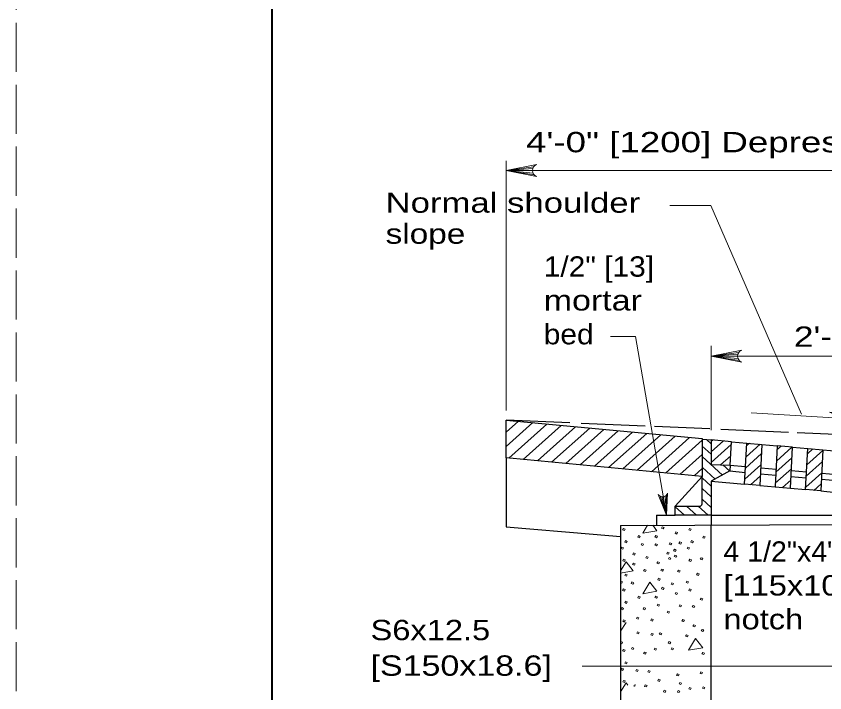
# Model space of a CAD drawing. Extents: x -1431.2 to -1397.2, y -1045.1 to -1001.1.
# Drawn here: x -1431.25 to -1424.93, y -1040.42 to -1035.13 of the extents above; entities that cross this region are included whole.
import ezdxf

# ---------------------------------------------------------------- set-up
doc = ezdxf.new("R2010")
doc.units = 0
doc.header["$LTSCALE"] = 0.064
doc.linetypes.add('LONG_DASHED', pattern=[7.5, 6, -1.5])
doc.layers.add('1', color=7, linetype='Continuous', lineweight=13)

msp = doc.modelspace()

# ---------------------------------------------------------------- linework, layer by layer
at = {"layer": '1'}
for p, q in [((-1427.4155, -1038.20883), (-1427.4155, -1036.25842)), ((-1427.20033, -1036.30475), (-1427.4155, -1036.33483)), ((-1427.20758, -1036.31967), (-1427.4155, -1036.33483)), ((-1423.10775, -1036.33483), (-1427.4155, -1036.33483)), ((-1427.20983, -1036.33483), (-1427.4155, -1036.33483)), ((-1427.206, -1036.35417), (-1427.4155, -1036.33483)), ((-1427.19775, -1036.36817), (-1427.4155, -1036.33483)), ((-1425.81283, -1038.363), (-1425.81283, -1037.705)), ((-1425.59767, -1037.75533), (-1425.81283, -1037.78542)), ((-1425.60492, -1037.77025), (-1425.81283, -1037.78542)), ((-1425.60717, -1037.78542), (-1425.81283, -1037.78542)), ((-1425.60333, -1037.80475), (-1425.81283, -1037.78542)), ((-1425.59508, -1037.81875), (-1425.81283, -1037.78542)), ((-1423.1035, -1037.78542), (-1425.81283, -1037.78542)), ((-1427.4155, -1038.38025), (-1427.32, -1038.29433)), ((-1427.4155, -1038.491), (-1427.20867, -1038.30483)), ((-1427.39458, -1038.58283), (-1427.09725, -1038.31533)), ((-1427.28325, -1038.59333), (-1426.98592, -1038.32583)), ((-1427.17183, -1038.60383), (-1426.87467, -1038.33633)), ((-1427.0605, -1038.61433), (-1426.76325, -1038.34683)), ((-1426.94908, -1038.62483), (-1426.65192, -1038.35733)), ((-1426.83775, -1038.63533), (-1426.5405, -1038.36775)), ((-1426.72642, -1038.64583), (-1426.42917, -1038.37833)), ((-1426.61508, -1038.65633), (-1426.31775, -1038.38883)), ((-1426.50375, -1038.66683), (-1426.20642, -1038.39933)), ((-1426.39233, -1038.67733), (-1426.09508, -1038.40975)), ((-1426.281, -1038.68783), (-1425.98367, -1038.42025)), ((-1426.16967, -1038.69833), (-1425.88467, -1038.44192)), ((-1425.88467, -1038.42967), (-1425.88467, -1038.43308)), ((-1425.81283, -1038.469), (-1425.84933, -1038.43617)), ((-1425.81283, -1038.45083), (-1425.80125, -1038.4405)), ((-1425.81283, -1038.534), (-1425.71733, -1038.448)), ((-1425.81283, -1038.55208), (-1425.88467, -1038.4875)), ((-1425.81283, -1038.617), (-1425.65617, -1038.476)), ((-1425.54133, -1038.57275), (-1425.431, -1038.4735)), ((-1425.537, -1038.48583), (-1425.515, -1038.46608)), ((-1425.3035, -1038.605), (-1425.18208, -1038.49567)), ((-1425.29925, -1038.51808), (-1425.266, -1038.48817)), ((-1425.06133, -1038.54817), (-1425.01908, -1038.51017)), ((-1426.05825, -1038.70883), (-1425.88467, -1038.55258)), ((-1425.72475, -1038.71433), (-1425.88467, -1038.5705)), ((-1425.73942, -1038.634), (-1425.6605, -1038.56292)), ((-1425.54575, -1038.65975), (-1425.42033, -1038.54683)), ((-1425.30783, -1038.69192), (-1425.1825, -1038.57917)), ((-1425.06575, -1038.63517), (-1424.94033, -1038.52233)), ((-1425.66733, -1038.683), (-1425.72125, -1038.6345)), ((-1425.55008, -1038.74675), (-1425.42467, -1038.63375)), ((-1425.07008, -1038.72208), (-1424.94467, -1038.60925)), ((-1425.94692, -1038.71933), (-1425.88467, -1038.66333)), ((-1425.78217, -1038.74575), (-1425.88467, -1038.6535)), ((-1425.31217, -1038.77875), (-1425.18683, -1038.66608)), ((-1425.07433, -1038.809), (-1424.94892, -1038.69617)), ((-1425.81283, -1038.80117), (-1425.88467, -1038.73658)), ((-1425.50583, -1038.78983), (-1425.429, -1038.72083)), ((-1425.25683, -1038.81208), (-1425.19125, -1038.753)), ((-1425.81283, -1038.88417), (-1425.88467, -1038.81958)), ((-1425.00992, -1038.834), (-1424.95325, -1038.78308)), ((-1426.212, -1038.87983), (-1426.1615, -1039.02842)), ((-1426.19958, -1038.88358), (-1426.1615, -1039.02842)), ((-1426.1875, -1038.88375), (-1426.1615, -1039.02842)), ((-1426.173, -1038.87933), (-1426.1615, -1039.02842)), ((-1426.16325, -1038.87217), (-1426.1615, -1039.02842)), ((-1426.02167, -1039.02842), (-1426.09542, -1038.962)), ((-1425.92942, -1039.02842), (-1426.00742, -1038.95817)), ((-1425.83717, -1039.02842), (-1425.91517, -1038.95817)), ((-1425.81283, -1038.96725), (-1425.88467, -1038.90267)), ((-1426.47917, -1039.39308), (-1426.52183, -1039.46183)), ((-1426.52183, -1039.54717), (-1426.52, -1039.54317)), ((-1426.47917, -1039.86608), (-1426.52183, -1039.93483)), ((-1426.52183, -1040.02008), (-1426.52, -1040.01608)), ((-1426.47917, -1040.339), (-1426.52183, -1040.40783)), ((-1426.46617, -1040.35575), (-1426.47917, -1040.339)), ((-1426.4115, -1040.35208), (-1426.40883, -1040.35317))]:
    msp.add_line(p, q, dxfattribs=at)
at = {"layer": '1', "lineweight": 25}
for p, q in [((-1426.91775, -1038.30683), (-1427.4155, -1038.28533)), ((-1427.4155, -1038.28533), (-1425.88425, -1038.42967)), ((-1426.3285, -1038.33242), (-1426.829, -1038.31067)), ((-1425.82308, -1038.35433), (-1426.25733, -1038.3355)), ((-1425.21017, -1038.38083), (-1425.73708, -1038.358)), ((-1424.63183, -1038.40583), (-1425.14108, -1038.38383)), ((-1425.65508, -1038.45358), (-1425.81283, -1038.4395)), ((-1425.66425, -1038.63642), (-1425.65508, -1038.45358)), ((-1425.65508, -1038.45358), (-1425.53592, -1038.46417)), ((-1425.41667, -1038.47475), (-1425.29758, -1038.48533)), ((-1425.17833, -1038.496), (-1425.05917, -1038.50658)), ((-1425.07533, -1038.82817), (-1425.05925, -1038.50658)), ((-1425.05917, -1038.50658), (-1424.93992, -1038.51717)), ((-1424.93992, -1038.51717), (-1424.82083, -1038.52775)), ((-1427.4155, -1038.58083), (-1427.4155, -1039.11925)), ((-1425.66733, -1038.63617), (-1425.54508, -1038.647)), ((-1425.6665, -1038.68258), (-1425.54742, -1038.69317)), ((-1425.42817, -1038.70375), (-1425.30892, -1038.71433)), ((-1425.42583, -1038.65767), (-1425.30667, -1038.66825)), ((-1425.1875, -1038.67892), (-1425.06842, -1038.6895)), ((-1424.94917, -1038.70008), (-1424.83008, -1038.71067)), ((-1425.88467, -1038.72525), (-1426.09542, -1038.95817)), ((-1425.88467, -1038.93858), (-1425.88467, -1038.72525)), ((-1425.81283, -1038.76258), (-1425.55208, -1038.78583)), ((-1425.18983, -1038.725), (-1425.07067, -1038.73567)), ((-1424.95142, -1038.74625), (-1424.83233, -1038.75683)), ((-1425.43283, -1038.79642), (-1425.31358, -1038.807)), ((-1425.1945, -1038.81758), (-1425.07533, -1038.82817)), ((-1424.95608, -1038.83883), (-1424.837, -1038.84942)), ((-1426.24008, -1039.02842), (-1426.24008, -1039.10625)), ((-1426.24008, -1039.02842), (-1426.09542, -1039.02842)), ((-1425.81283, -1039.02842), (-1423.1035, -1039.02842)), ((-1426.52183, -1039.1075), (-1422.72758, -1039.09133)), ((-1426.52183, -1039.1075), (-1426.52183, -1041.37567)), ((-1425.81283, -1040.04383), (-1425.81283, -1039.1045)), ((-1425.81283, -1041.37325), (-1425.81283, -1040.04383))]:
    msp.add_line(p, q, dxfattribs=at)
at = {"layer": '1', "linetype": 'LONG_DASHED'}
msp.add_lwpolyline([(-1431.24575, -1045.07983), (-1397.24575, -1045.07983), (-1397.24575, -1023.07983), (-1431.24575, -1023.07983)], close=True, dxfattribs=at)
at = {"layer": '1', "lineweight": 25}
for points in [[(-1397.74575, -1044.57983), (-1429.24575, -1044.57983), (-1429.24575, -1023.57983)], [(-1425.88467, -1038.42967), (-1425.88467, -1038.72525), (-1427.4155, -1038.58083), (-1427.4155, -1038.28533)], [(-1425.88467, -1038.43308), (-1425.81283, -1038.4395), (-1425.81283, -1038.63175), (-1425.66733, -1038.63617)], [(-1424.94, -1038.51717), (-1424.95608, -1038.83883), (-1425.07533, -1038.82817)], [(-1425.66417, -1038.63642), (-1425.6665, -1038.68258), (-1425.81283, -1038.7625), (-1425.81283, -1039.1045)], [(-1425.81283, -1039.02842), (-1426.09542, -1039.02842), (-1426.09542, -1038.95817), (-1425.90633, -1038.95817)], [(-1427.4155, -1039.11925), (-1426.73658, -1039.17567), (-1426.52183, -1039.1935)]]:
    msp.add_lwpolyline(points, dxfattribs=at)
at = {"layer": '1', "lineweight": 40}
msp.add_lwpolyline([(-1429.24575, -1023.57983), (-1397.74575, -1023.57983), (-1397.74575, -1044.57983), (-1429.24575, -1044.57983)], close=True, dxfattribs=at)
at = {"layer": '1'}
for points in [[(-1427.17783, -1036.38242), (-1427.4155, -1036.33483), (-1427.17783, -1036.28733)], [(-1425.10825, -1038.23842), (-1425.81675, -1036.60825), (-1426.13675, -1036.60825)], [(-1426.1615, -1039.02842), (-1426.40542, -1037.63133), (-1426.5995, -1037.63133)], [(-1425.57508, -1037.833), (-1425.81283, -1037.78542), (-1425.57508, -1037.73792)], [(-1425.502, -1038.22842), (-1424.33817, -1038.29833), (-1424.88758, -1038.22325), (-1424.77525, -1038.27042)], [(-1426.15475, -1038.85675), (-1426.1615, -1039.02842), (-1426.22833, -1038.86558)], [(-1426.31008, -1039.10658), (-1426.34867, -1039.16883), (-1426.23725, -1039.14925), (-1426.27058, -1039.10642)], [(-1426.52183, -1039.48125), (-1426.42392, -1039.464), (-1426.47917, -1039.39308)], [(-1426.52, -1039.54317), (-1426.50633, -1039.548), (-1426.51183, -1039.56025), (-1426.52183, -1039.556)], [(-1422.76167, -1039.67058), (-1424.21225, -1040.20775), (-1426.82292, -1040.20775)], [(-1426.52, -1040.01608), (-1426.50633, -1040.021), (-1426.51183, -1040.03325), (-1426.52183, -1040.029)], [(-1426.40883, -1040.35592), (-1426.41392, -1040.36517), (-1426.42183, -1040.36233)]]:
    msp.add_lwpolyline(points, dxfattribs=at)
at = {"layer": '1', "lineweight": 25}
for points in [[(-1425.55208, -1038.78583), (-1425.53592, -1038.46417), (-1425.41667, -1038.47475), (-1425.43283, -1038.79642)], [(-1425.17833, -1038.496), (-1425.29758, -1038.48533), (-1425.31358, -1038.807), (-1425.1945, -1038.81758)]]:
    msp.add_lwpolyline(points, close=True, dxfattribs=at)
at = {"layer": '1'}
for points in [[(-1426.49908, -1039.13133), (-1426.4855, -1039.13625), (-1426.49183, -1039.14758), (-1426.50542, -1039.14275)], [(-1426.1955, -1039.11825), (-1426.18192, -1039.124), (-1426.18825, -1039.13542), (-1426.20192, -1039.1305)], [(-1425.98258, -1039.13133), (-1425.969, -1039.13625), (-1425.97533, -1039.14758), (-1425.98892, -1039.14275)], [(-1426.38225, -1039.18758), (-1426.36858, -1039.19325), (-1426.37408, -1039.20467), (-1426.38767, -1039.19983)], [(-1426.24717, -1039.18758), (-1426.23358, -1039.1925), (-1426.23992, -1039.20392), (-1426.2535, -1039.199)], [(-1426.0895, -1039.15825), (-1426.07592, -1039.16308), (-1426.08133, -1039.17533), (-1426.09492, -1039.16967)], [(-1425.873, -1039.19242), (-1425.85942, -1039.19733), (-1425.86575, -1039.20875), (-1425.87942, -1039.20383)], [(-1426.51267, -1039.27725), (-1426.49908, -1039.283), (-1426.50458, -1039.29442), (-1426.51817, -1039.28867)], [(-1426.48275, -1039.22675), (-1426.46917, -1039.23242), (-1426.47558, -1039.24383), (-1426.48917, -1039.23817)], [(-1426.355, -1039.24875), (-1426.34142, -1039.25442), (-1426.34692, -1039.26583), (-1426.3605, -1039.26017)], [(-1426.24717, -1039.25117), (-1426.23358, -1039.25608), (-1426.23992, -1039.26833), (-1426.2535, -1039.26258)], [(-1426.13575, -1039.243), (-1426.12217, -1039.24875), (-1426.12758, -1039.26017), (-1426.14117, -1039.25525)], [(-1426.05867, -1039.2365), (-1426.04508, -1039.24142), (-1426.05142, -1039.25367), (-1426.06508, -1039.24792)], [(-1425.99617, -1039.27725), (-1425.98258, -1039.283), (-1425.988, -1039.29442), (-1426.00158, -1039.28867)], [(-1425.96625, -1039.22675), (-1425.95267, -1039.23242), (-1425.959, -1039.24383), (-1425.97258, -1039.23817)], [(-1426.42025, -1039.32217), (-1426.40667, -1039.32783), (-1426.41208, -1039.33925), (-1426.42575, -1039.33433)], [(-1426.15567, -1039.31725), (-1426.14208, -1039.32217), (-1426.1475, -1039.33358), (-1426.16108, -1039.32867)], [(-1426.10125, -1039.29442), (-1426.08767, -1039.30008), (-1426.09317, -1039.3115), (-1426.10675, -1039.30667)], [(-1426.09675, -1039.33925), (-1426.08317, -1039.345), (-1426.08858, -1039.35642), (-1426.10217, -1039.35067)], [(-1426.49817, -1039.37267), (-1426.48458, -1039.37758), (-1426.49008, -1039.38983), (-1426.50367, -1039.38408)], [(-1426.42117, -1039.40208), (-1426.40758, -1039.40775), (-1426.41392, -1039.41917), (-1426.4275, -1039.41425)], [(-1426.31875, -1039.34983), (-1426.30517, -1039.35475), (-1426.3115, -1039.367), (-1426.32508, -1039.36125)], [(-1426.23175, -1039.39225), (-1426.21817, -1039.39717), (-1426.22367, -1039.40858), (-1426.23725, -1039.40367)], [(-1426.14117, -1039.358), (-1426.12758, -1039.36375), (-1426.133, -1039.37517), (-1426.14658, -1039.36942)], [(-1425.98167, -1039.37267), (-1425.96808, -1039.37758), (-1425.9735, -1039.38983), (-1425.98708, -1039.38408)], [(-1425.89217, -1039.36), (-1425.87858, -1039.36483), (-1425.88492, -1039.37625), (-1425.8985, -1039.37142)], [(-1426.336, -1039.45183), (-1426.32242, -1039.45667), (-1426.32783, -1039.46808), (-1426.34142, -1039.46325)], [(-1426.201, -1039.4485), (-1426.18742, -1039.45342), (-1426.19375, -1039.46483), (-1426.20733, -1039.45992)], [(-1426.06958, -1039.45667), (-1426.056, -1039.46158), (-1426.06233, -1039.473), (-1426.07592, -1039.46808)], [(-1426.48275, -1039.4885), (-1426.46917, -1039.49342), (-1426.47467, -1039.50558), (-1426.48825, -1039.49992)], [(-1426.22542, -1039.52108), (-1426.21183, -1039.526), (-1426.21725, -1039.53742), (-1426.23092, -1039.5325)], [(-1425.92092, -1039.48208), (-1425.90733, -1039.48692), (-1425.91367, -1039.49833), (-1425.92725, -1039.4935)], [(-1426.433, -1039.54967), (-1426.41933, -1039.55533), (-1426.42483, -1039.56675), (-1426.43842, -1039.56192)], [(-1426.2925, -1039.55125), (-1426.34867, -1039.64183), (-1426.23725, -1039.62225)], [(-1426.1955, -1039.59125), (-1426.18192, -1039.59692), (-1426.18825, -1039.60833), (-1426.20192, -1039.6035)], [(-1426.12033, -1039.55533), (-1426.10675, -1039.56108), (-1426.11217, -1039.5725), (-1426.12575, -1039.56675)], [(-1426.00342, -1039.54317), (-1425.98983, -1039.548), (-1425.99525, -1039.56025), (-1426.00883, -1039.55458)], [(-1426.49908, -1039.60433), (-1426.4855, -1039.60917), (-1426.49183, -1039.62058), (-1426.50542, -1039.61567)], [(-1426.0895, -1039.63117), (-1426.07592, -1039.63608), (-1426.08133, -1039.64833), (-1426.09492, -1039.64258)], [(-1425.98258, -1039.60433), (-1425.969, -1039.60917), (-1425.97533, -1039.62058), (-1425.98892, -1039.61567)], [(-1426.48275, -1039.69967), (-1426.46917, -1039.70542), (-1426.47558, -1039.71683), (-1426.48917, -1039.71108)], [(-1426.38225, -1039.66058), (-1426.36858, -1039.66625), (-1426.37408, -1039.67767), (-1426.38767, -1039.67283)], [(-1426.24717, -1039.66058), (-1426.23358, -1039.66542), (-1426.23992, -1039.67683), (-1426.2535, -1039.672)], [(-1425.89217, -1039.67592), (-1425.87858, -1039.68083), (-1425.88492, -1039.69225), (-1425.8985, -1039.68733)], [(-1426.51267, -1039.75025), (-1426.49908, -1039.756), (-1426.50458, -1039.76742), (-1426.51817, -1039.76167)], [(-1426.34075, -1039.7505), (-1426.32717, -1039.75542), (-1426.33258, -1039.76683), (-1426.34625, -1039.76192)], [(-1426.23033, -1039.7235), (-1426.21675, -1039.72842), (-1426.22217, -1039.73983), (-1426.23575, -1039.73492)], [(-1426.15183, -1039.7775), (-1426.13825, -1039.78242), (-1426.14367, -1039.79383), (-1426.15725, -1039.78892)], [(-1426.05858, -1039.72842), (-1426.045, -1039.73333), (-1426.05042, -1039.74475), (-1426.064, -1039.73983)], [(-1425.9555, -1039.73333), (-1425.94192, -1039.73825), (-1425.94733, -1039.74967), (-1425.96092, -1039.74475)], [(-1426.49817, -1039.84567), (-1426.48458, -1039.85058), (-1426.49008, -1039.86283), (-1426.50367, -1039.85708)], [(-1426.39233, -1039.82417), (-1426.37875, -1039.829), (-1426.38417, -1039.84042), (-1426.39775, -1039.83558)], [(-1426.27942, -1039.83883), (-1426.26583, -1039.84375), (-1426.27125, -1039.85517), (-1426.28483, -1039.85025)], [(-1426.03583, -1039.8435), (-1426.02225, -1039.84842), (-1426.02858, -1039.85983), (-1426.04217, -1039.85492)], [(-1425.94967, -1039.88417), (-1425.93608, -1039.88908), (-1425.94242, -1039.9005), (-1425.956, -1039.89558)], [(-1426.38983, -1039.9395), (-1426.37625, -1039.94433), (-1426.38167, -1039.95575), (-1426.39525, -1039.95092)], [(-1426.28, -1039.95125), (-1426.26642, -1039.95608), (-1426.27275, -1039.9675), (-1426.28633, -1039.96267)], [(-1426.21292, -1039.94642), (-1426.19933, -1039.95133), (-1426.20567, -1039.96275), (-1426.21925, -1039.95783)], [(-1426.00708, -1039.96317), (-1425.9935, -1039.96808), (-1425.99983, -1039.9795), (-1426.01342, -1039.97458)], [(-1425.885, -1039.92008), (-1425.87142, -1039.925), (-1425.87775, -1039.93642), (-1425.89133, -1039.9315)], [(-1426.1435, -1040.01583), (-1426.12992, -1040.02075), (-1426.13625, -1040.03217), (-1426.14983, -1040.02725)], [(-1425.93525, -1039.99275), (-1425.99142, -1040.08325), (-1425.88, -1040.06367)], [(-1426.49908, -1040.07725), (-1426.4855, -1040.08217), (-1426.49183, -1040.09358), (-1426.50542, -1040.08867)], [(-1426.43158, -1040.06217), (-1426.418, -1040.06708), (-1426.42342, -1040.0785), (-1426.437, -1040.07358)], [(-1426.335, -1040.09725), (-1426.32142, -1040.10217), (-1426.32775, -1040.1135), (-1426.34133, -1040.10867)], [(-1426.25342, -1040.06667), (-1426.23983, -1040.07158), (-1426.24617, -1040.083), (-1426.25975, -1040.07808)], [(-1426.12067, -1040.06442), (-1426.10708, -1040.06933), (-1426.11342, -1040.08075), (-1426.127, -1040.07583)], [(-1425.87925, -1040.10067), (-1425.86567, -1040.1055), (-1425.872, -1040.11692), (-1425.88567, -1040.11208)], [(-1426.51267, -1040.22325), (-1426.49908, -1040.22892), (-1426.50458, -1040.24033), (-1426.51817, -1040.23467)], [(-1426.48275, -1040.17267), (-1426.46917, -1040.17842), (-1426.47558, -1040.18983), (-1426.48917, -1040.18408)], [(-1426.39725, -1040.23392), (-1426.38358, -1040.23883), (-1426.38908, -1040.25025), (-1426.40267, -1040.24533)], [(-1426.304, -1040.24133), (-1426.29042, -1040.24617), (-1426.29583, -1040.25758), (-1426.30942, -1040.25275)], [(-1426.07725, -1040.26817), (-1426.06358, -1040.27308), (-1426.07, -1040.2845), (-1426.08358, -1040.27958)], [(-1425.89375, -1040.25233), (-1425.88017, -1040.25717), (-1425.8865, -1040.26858), (-1425.90008, -1040.26375)], [(-1426.49817, -1040.31867), (-1426.48458, -1040.32358), (-1426.49008, -1040.33575), (-1426.50367, -1040.33008)], [(-1426.3285, -1040.35417), (-1426.31492, -1040.35908), (-1426.32033, -1040.3705), (-1426.33392, -1040.36558)], [(-1426.22542, -1040.31), (-1426.21183, -1040.31492), (-1426.21725, -1040.32633), (-1426.23092, -1040.32142)], [(-1426.05858, -1040.33458), (-1426.045, -1040.33942), (-1426.05042, -1040.35083), (-1426.064, -1040.346)], [(-1426.18125, -1040.39592), (-1426.16767, -1040.40083), (-1426.17308, -1040.41225), (-1426.18667, -1040.40733)], [(-1426.07083, -1040.39833), (-1426.05725, -1040.40325), (-1426.06267, -1040.41467), (-1426.07625, -1040.40975)], [(-1425.9825, -1040.37383), (-1425.96892, -1040.37875), (-1425.97433, -1040.39017), (-1425.98792, -1040.38525)], [(-1425.877, -1040.36892), (-1425.86342, -1040.37383), (-1425.86883, -1040.38525), (-1425.88242, -1040.38033)]]:
    msp.add_lwpolyline(points, close=True, dxfattribs=at)
for centre in [(-1427.1586, -1036.33482), (-1425.55593, -1037.7854)]:
    msp.add_arc(centre, 0.05131, 112.08782, 247.91395, dxfattribs=at)
msp.add_ellipse((-1426.19395, -1038.84766), major_axis=(-0.0399, 0.0059), ratio=0.899905, start_param=0.6793746, end_param=3.0499877, dxfattribs=at)
at = {"layer": '1', "lineweight": 25}
msp.add_ellipse((-1425.90638, -1038.93862), major_axis=(0.02175, 0), ratio=0.899905, start_param=4.712389, end_param=6.2831853, dxfattribs=at)

# ---------------------------------------------------------------- texts
at = {"layer": '1'}
for s, height, width, p in [('4\'-0" [1200] Depressed Apron', 0.1588, 1.35, (-1427.26092, -1036.19192)), ('Normal shoulder', 0.156, 1.3, (-1428.35825, -1036.66433)), ('slope ', 0.156, 1.25, (-1428.35825, -1036.90683)), ('1/2" [13]', 0.1588, 1.1, (-1427.12217, -1037.164)), ('mortar', 0.1588, 1.25, (-1427.12217, -1037.42842)), ('bed', 0.1588, 1.1, (-1427.12217, -1037.69283)), ('2\'-6" [750]', 0.1588, 1.3, (-1425.16692, -1037.71208)), ('4 1/2"x4"x11\'-0"', 0.1588, 1.05, (-1425.71767, -1039.39125)), ('[115x100x1115]', 0.1588, 1.2, (-1425.71767, -1039.65567)), ('notch', 0.1588, 1.2, (-1425.71767, -1039.92008)), ('S6x12.5', 0.1588, 1.2, (-1428.47583, -1040.00467)), ('[S150x18.6]', 0.1588, 1.25, (-1428.47583, -1040.2825))]:
    msp.add_text(s, height=height, dxfattribs=dict(at, width=width)).set_placement(p)

doc.saveas('drawing.dxf')
